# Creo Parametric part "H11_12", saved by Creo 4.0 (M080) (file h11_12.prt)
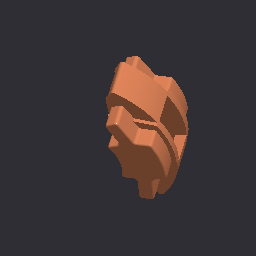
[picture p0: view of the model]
Units: Inch lbm Second (Pro/E Default); INCH, POUND, SECS

Other parameters: D33

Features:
  1. datum plane "DTM1"
  2. datum plane "DTM2"
  3. datum plane "DTM3"
  4. datum axis
  5. protrusion
  6. cut
  7. protrusion
  8. protrusion
  9. protrusion
  10. cut
  11. cut
  12. cut
  13. pattern
  14. protrusion
  15. protrusion
  16. round
  17. round
  18. round
  19. round
  20. round
  21. round

Other named items: WHEEL_AXIS

Layers: BASE_DAT, BLANK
